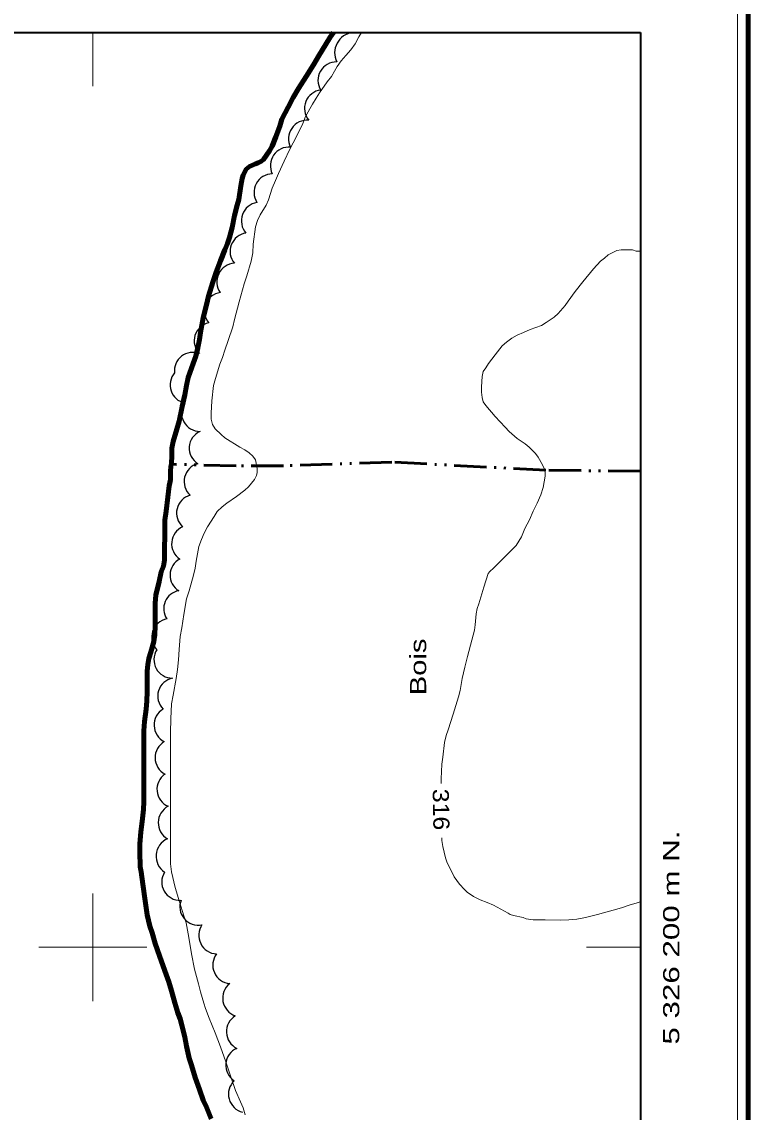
# Model space of a CAD drawing. Extents: x 240591 to 242335, y 5323482 to 5326937.
# Drawn here: x 242186.8 to 242321.7, y 5326169.4 to 5326371.9 of the extents above; entities that cross this region are included whole.
import ezdxf
from ezdxf.enums import TextEntityAlignment as Align

# ---------------------------------------------------------------- set-up
doc = ezdxf.new("R2010")
doc.units = 0
doc.header["$LTSCALE"] = 1.2
doc.linetypes.add('DASH_DOUBLE_DOT', pattern=[9.2, 5, -1.2, 0.3, -1.2, 0.3, -1.2])
doc.linetypes.add('LONG_DASHED', pattern=[7.5, 6, -1.5])
for name, color, linetype, lineweight in [('2', 7, 'Continuous', 13), ('4', 7, 'DASH_DOUBLE_DOT', 53), ('44', 7, 'Continuous', 25), ('60', 7, 'Continuous', 35), ('61', 7, 'Continuous', 13)]:
    doc.layers.add(name, color=color, linetype=linetype, lineweight=lineweight)

msp = doc.modelspace()

# ---------------------------------------------------------------- linework, layer by layer
at = {"layer": '2'}
for points in [[(242229.8, 5326330.6), (242230.2, 5326333.8), (242230.6, 5326335), (242231.1, 5326336), (242232.2, 5326337.8), (242232.6, 5326338.8), (242233.3, 5326341), (242233.9, 5326342.4), (242234.5, 5326343.7), (242235.5, 5326346), (242236.6, 5326348.2), (242237.8, 5326350.6), (242239, 5326353), (242239.5, 5326354.3), (242240.8, 5326356.6), (242241.5, 5326357.7), (242242.1, 5326358.7), (242243.5, 5326360.7), (242244.3, 5326361.7), (242244.9, 5326362.7), (242245.4, 5326363.6), (242246.1, 5326364.6), (242247, 5326365.6), (242247.9, 5326366.7), (242248.7, 5326367.8), (242249.4, 5326369.1), (242249.9, 5326369.9)], [(242228.3, 5326168.9), (242227.9, 5326170.2), (242227.4, 5326171.3), (242226.5, 5326173.4), (242225.6, 5326175.9), (242224.7, 5326178.7), (242223.7, 5326181.5), (242222.7, 5326184.1), (242221.6, 5326186.8), (242220.9, 5326188.6), (242220.6, 5326189.6), (242220, 5326191.7), (242219.6, 5326193.2), (242218.9, 5326195.9), (242218.3, 5326198.8), (242217.8, 5326201.8), (242217.3, 5326204.5), (242216.9, 5326205.8), (242216.1, 5326208.4), (242215.3, 5326211.1), (242214.6, 5326214), (242214.4, 5326215.5), (242214.4, 5326216.9), (242214.4, 5326219.9), (242214.4, 5326222.8), (242214.4, 5326226.1), (242214.4, 5326229.4), (242214.4, 5326233), (242214.4, 5326236.2), (242214.4, 5326239.9), (242214.5, 5326242.4), (242214.6, 5326245.2), (242214.9, 5326246.8), (242215.5, 5326249.9), (242215.7, 5326251.6), (242215.9, 5326253.4), (242216, 5326255.3), (242216.2, 5326257.7), (242216.5, 5326259.3), (242216.9, 5326261.8), (242217.4, 5326264.7), (242217.9, 5326266.2), (242218.7, 5326269.1), (242219, 5326270.4), (242219.2, 5326271.7), (242219.7, 5326274.4), (242220.2, 5326275.7), (242220.7, 5326276.9), (242221.3, 5326278.1), (242222.5, 5326280), (242223.1, 5326280.9), (242224, 5326281.8), (242224.9, 5326282.5), (242226.7, 5326283.7), (242228.2, 5326284.9), (242228.9, 5326285.5), (242230, 5326286.9), (242230.4, 5326287.6), (242230.5, 5326288.2), (242230.5, 5326288.9), (242230.2, 5326290.5), (242229.7, 5326291.2), (242229, 5326291.8), (242228.2, 5326292.4), (242227.3, 5326292.9), (242224.5, 5326294.6), (242223.8, 5326295.2), (242222.7, 5326296.3), (242222.2, 5326297.1), (242222, 5326298.1), (242222, 5326299.2), (242222.1, 5326301.5), (242222.4, 5326304.3), (242222.8, 5326305.6), (242223.6, 5326308.3), (242224.1, 5326309.5), (242224.5, 5326310.9), (242225.1, 5326312.7), (242226, 5326315.2), (242226.3, 5326316.6), (242227.2, 5326319.9), (242228.1, 5326323.2), (242228.6, 5326324.7), (242229.4, 5326327.4), (242229.7, 5326329), (242229.8, 5326330.6)]]:
    msp.add_lwpolyline(points, dxfattribs=at)
at = {"layer": '2', "linetype": 'LONG_DASHED'}
for points in [[(242272.3, 5326306), (242272.5, 5326306.9), (242273, 5326307.6), (242273.5, 5326308.4), (242274.7, 5326310), (242276, 5326311.7), (242276.8, 5326312.4), (242277.8, 5326313.1), (242278.8, 5326313.7), (242280, 5326314.2), (242281.2, 5326314.7), (242283.3, 5326315.5), (242284.2, 5326316), (242285.7, 5326317), (242286.4, 5326317.7), (242287.7, 5326319.2), (242288.3, 5326320), (242289.6, 5326321.8), (242291, 5326323.6), (242293, 5326326), (242294.3, 5326327.4), (242295, 5326328), (242295.7, 5326328.6), (242297.3, 5326329.4), (242298.1, 5326329.5), (242298.8, 5326329.5), (242300.2, 5326329.5), (242300.9, 5326329.3), (242301.7, 5326329.3)], [(242264.7, 5326230.4), (242264.7, 5326231.3), (242264.8, 5326234), (242265, 5326235.3), (242265.3, 5326238), (242265.6, 5326239.3), (242266, 5326240.4), (242266.9, 5326243.3), (242267.9, 5326246.5), (242268.2, 5326247.7), (242268.6, 5326249.9), (242269.1, 5326252), (242269.6, 5326254), (242270.4, 5326257), (242270.9, 5326258.9), (242271, 5326259.9), (242271.2, 5326261.9), (242271.4, 5326262.9), (242271.7, 5326263.8), (242272.6, 5326266.9), (242273.4, 5326269.4), (242273.7, 5326269.8), (242274.4, 5326270.4), (242275.7, 5326271.7), (242277.2, 5326273.2), (242278.6, 5326274.6), (242279.1, 5326275.4), (242279.6, 5326276.2), (242280.2, 5326277.8), (242281.1, 5326279.4), (242281.8, 5326281), (242282.5, 5326282.5), (242283.2, 5326284), (242283.6, 5326285.4), (242284, 5326287.5), (242284, 5326288.2), (242283.8, 5326288.9), (242283.5, 5326289.6), (242282.7, 5326291), (242282.2, 5326291.7), (242281, 5326292.9), (242280.3, 5326293.5), (242278.8, 5326294.5), (242277.3, 5326295.8), (242276.6, 5326296.6), (242274.7, 5326298.6), (242273, 5326300.6), (242272.5, 5326301.3), (242272.3, 5326302.1), (242272.2, 5326303.1), (242272.2, 5326304.1), (242272.3, 5326306)], [(242301.7, 5326208.5), (242301.3, 5326208.3), (242299.8, 5326207.9), (242298.2, 5326207.3), (242296.6, 5326206.9), (242293.7, 5326206.1), (242291.5, 5326205.5), (242289.9, 5326205.2), (242288.4, 5326205.1), (242286.8, 5326205), (242284, 5326205.1), (242281.8, 5326205.1), (242280.5, 5326205.3), (242279.9, 5326205.5), (242278.1, 5326205.9), (242277.5, 5326206.1), (242277.1, 5326206.3), (242274.4, 5326207.8), (242273.2, 5326208.3), (242271.9, 5326208.8), (242270.7, 5326209.4), (242269.5, 5326210.2), (242269, 5326210.7), (242268.1, 5326211.7), (242267.1, 5326213.1), (242266.7, 5326213.9), (242265.8, 5326215.7), (242265.5, 5326216.6), (242265, 5326218.7), (242264.8, 5326219.8), (242264.8, 5326220.3)]]:
    msp.add_lwpolyline(points, dxfattribs=at)
at = {"layer": '4', "linetype": 'Continuous', "lineweight": 90}
for points in [[(242244.7, 5326369.9), (242244.1, 5326369), (242243.2, 5326367.6), (242242, 5326365.7), (242241, 5326363.9), (242239.6, 5326361.7), (242238.2, 5326359.5), (242237.2, 5326357.8), (242236.3, 5326356), (242235.1, 5326353.8), (242234.7, 5326352.5), (242234, 5326350.5), (242233.3, 5326348.8), (242232.8, 5326347.9), (242231.7, 5326346.3), (242231.3, 5326346), (242230.7, 5326345.7), (242230.2, 5326345.5), (242229.1, 5326345), (242228.5, 5326344.5), (242228.2, 5326344), (242227.9, 5326343.4), (242227.7, 5326342.8), (242227.5, 5326341.4), (242227.1, 5326338.9), (242226.8, 5326337.8), (242226.3, 5326335.9), (242225.9, 5326333.7), (242225.4, 5326331.8), (242225, 5326330.7), (242224.5, 5326329.5), (242223.7, 5326327.5), (242222.9, 5326325.4), (242222.3, 5326323.5), (242221.5, 5326320.9), (242221.1, 5326319.3), (242220.5, 5326316.9), (242220, 5326314.2), (242219.8, 5326312.9), (242219.5, 5326311.3), (242219.1, 5326309.8), (242218.6, 5326308.4), (242217.7, 5326305.8), (242217.4, 5326304.3), (242217.1, 5326302.6), (242216.6, 5326300.4), (242216, 5326297.7), (242215.6, 5326296.2), (242214.9, 5326293.9), (242214.7, 5326292.7), (242214.7, 5326291.4), (242214.6, 5326289.7)], [(242214.4, 5326288.3), (242214.4, 5326286.8), (242214.2, 5326285.7), (242213.9, 5326283.6), (242213.6, 5326281), (242213.4, 5326279.3), (242213.4, 5326277.9), (242213.4, 5326276.1), (242213.3, 5326274.4), (242213.3, 5326271.9), (242213.1, 5326270.8), (242212.7, 5326269.7), (242212.3, 5326267.9), (242211.7, 5326265.4), (242211.6, 5326263.9), (242211.6, 5326262.3), (242211.6, 5326259.7), (242211.5, 5326258), (242211.3, 5326256.8), (242210.8, 5326254.8), (242210.4, 5326253.6), (242210.2, 5326252.5), (242210.1, 5326251.3), (242210.1, 5326249.9), (242210.1, 5326247.5), (242210, 5326245.7), (242209.9, 5326244.2), (242209.6, 5326241.9), (242209.5, 5326240.2), (242209.5, 5326238.2), (242209.5, 5326235.1), (242209.5, 5326232.5), (242209.5, 5326229.8), (242209.5, 5326227), (242209.4, 5326225.6), (242209.2, 5326223.9), (242208.9, 5326221.4), (242208.7, 5326219.2), (242208.7, 5326217.7), (242208.8, 5326214.9), (242209, 5326214), (242209.3, 5326211.7), (242209.7, 5326208.6), (242210.1, 5326206), (242210.6, 5326203.9), (242211, 5326202.7), (242211.6, 5326200.7), (242212.4, 5326198.4), (242213.4, 5326195.6), (242214.1, 5326193.6), (242214.6, 5326191.9), (242215.2, 5326189.7), (242215.8, 5326187.8), (242216.2, 5326186.7), (242216.5, 5326185.5), (242217.1, 5326183.3), (242217.4, 5326181.6), (242217.9, 5326179.4), (242218.3, 5326178.1), (242219, 5326175.8), (242219.8, 5326173.6), (242220.5, 5326171.6), (242221.1, 5326170.3), (242222, 5326168.1)], [(242214.6, 5326289.7), (242214.5, 5326289.4), (242214.4, 5326288.3)]]:
    msp.add_lwpolyline(points, dxfattribs=at)
at = {"layer": '4'}
msp.add_lwpolyline([(242301.7, 5326288.4), (242284.1, 5326288.6), (242255.5, 5326290.1), (242235.4, 5326289.4), (242226.6, 5326289.4), (242214.6, 5326289.7)], dxfattribs=at)
at = {"layer": '44'}
for centre, radius, start, end in [((242248.723, 5326366.11), 3.822, 97.47329, 206.0815), ((242245.241, 5326360.997), 3.433, 89.18247, 211.37505), ((242242.753, 5326355.794), 3.445, 97.39742, 219.35299), ((242231.044, 5326334.907), 3.459, 99.39087, 221.16121), ((242224.145, 5326318.183), 3.441, 98.10329, 220.02678), ((242222.231, 5326312.639), 3.409, 102.21586, 224.01713), ((242220.404, 5326286.477), 3.454, 105.1792, 227.25413), ((242214.836, 5326241.264), 3.459, 121.28851, 243.07297), ((242215, 5326235.206), 3.44, 120.18027, 242.29391), ((242215.344, 5326229.323), 3.439, 124.42069, 246.45095), ((242228.268, 5326184.315), 3.452, 121.78128, 243.72551)]:
    msp.add_arc(centre, radius, start, end, dxfattribs=at)
for centre, major_axis, ratio, start_param, end_param in [((242239.799, 5326350.17), (-0.197, -3.446), 0.999995, 3.1142531, 5.2450033), ((242236.402, 5326345.166), (-2.622, 2.227), 0.999596, 5.3206974, 7.4473389), ((242233.382, 5326340.189), (0.138, -3.449), 0.999995, 3.1195613, 5.2445601), ((242228.919, 5326329.225), (2.183, -2.657), 0.999984, 2.5936542, 4.7204313), ((242226.471, 5326323.581), (0.285, -3.433), 0.999995, 3.1142291, 5.2456293), ((242218.572, 5326307.071), (-2.578, -2.246), 0.999753, 3.634719, 5.6856978), ((242217.762, 5326304.438), (0.931, -3.29), 0.999938, 3.7256325, 5.788689), ((242219.883, 5326299.23), (1.635, -3.004), 0.999861, 3.6352066, 5.7895712), ((242221.306, 5326292.703), (-0.227, -3.403), 0.999753, 3.6331462, 5.7916317), ((242218.987, 5326280.626), (-3.346, 0.807), 0.999801, 5.2216763, 7.348405), ((242218.068, 5326274.95), (-3.428, 0.302), 0.999911, 5.2218424, 7.3470225), ((242217.754, 5326269.09), (0, -3.415), 0.999753, 3.633808, 5.7271318), ((242216.575, 5326262.865), (-1.607, -3.015), 0.999752, 3.8078177, 5.7891675), ((242214.364, 5326257.609), (-1.046, -3.258), 0.999751, 3.6381106, 5.7866674), ((242214.754, 5326253.391), (-2.47, -2.356), 0.998921, 4.9469885, 7.1031628), ((242215.466, 5326246.629), (-0.994, -3.271), 0.999752, 3.635639, 5.789139), ((242215.596, 5326223.129), (-3.456, 0.039), 0.996837, 5.2134502, 7.3389581), ((242215.323, 5326216.886), (-3.272, 1.445), 0.999964, 5.5497432, 7.6722565), ((242216.218, 5326212.126), (1.7, -2.97), 0.999938, 3.6374762, 5.7873018), ((242219.571, 5326207.517), (2.204, -2.613), 0.999938, 3.6363271, 5.7884508), ((242223.125, 5326202.216), (-3.094, -1.547), 0.999978, 5.2193403, 7.345551), ((242225.729, 5326196.681), (-3.159, -1.4), 0.999731, 5.2200659, 7.3475805), ((242227.593, 5326190.53), (2.246, -2.65), 0.999995, 3.1144058, 5.2447642), ((242228.152, 5326178.069), (-3.442, 0.291), 0.999556, 5.2177554, 7.3481972), ((242228.652, 5326172.723), (-3.458, 0.21), 0.999962, 5.5472771, 7.6722203)]:
    msp.add_ellipse(centre, major_axis=major_axis, ratio=ratio, start_param=start_param, end_param=end_param, dxfattribs=at)
at = {"layer": '60', "lineweight": 158}
msp.add_lwpolyline([(242321.7, 5323482.5), (240590.8, 5323482.5), (240590.8, 5326907.9), (242321.7, 5326907.9)], close=True, dxfattribs=at)
at = {"layer": '60', "lineweight": 13}
msp.add_lwpolyline([(240592.8, 5323484.5), (240592.8, 5326905.9), (242319.7, 5326905.9), (242319.7, 5323484.5)], close=True, dxfattribs=at)
at = {"layer": '60'}
msp.add_lwpolyline([(240610.8, 5326369.9), (242301.7, 5326369.9), (242301.7, 5323502.5), (240610.8, 5323502.5)], close=True, dxfattribs=at)
at = {"layer": '61'}
for p, q in [((242200, 5326369.9), (242200, 5326359.9)), ((242301.7, 5326200), (242291.7, 5326200))]:
    msp.add_line(p, q, dxfattribs=at)
for points in [[(242200, 5326210), (242200, 5326200), (242200, 5326190)], [(242190, 5326200), (242200, 5326200), (242210, 5326200)]]:
    msp.add_lwpolyline(points, dxfattribs=at)

# ---------------------------------------------------------------- texts
at = {"layer": '2', "width": 1.15}
msp.add_text('316', height=3, rotation=271.109, dxfattribs=at).set_placement((242263.1, 5326229.4))
at = {"layer": '44', "width": 1.35}
msp.add_text('Bois', height=3, rotation=90, dxfattribs=at).set_placement((242261.9, 5326246.8))
at = {"layer": '61', "width": 1.45}
msp.add_text('5 326 200 m N.', height=3, rotation=90, dxfattribs=at).set_placement((242308.9, 5326201.8), align=Align.CENTER)

doc.saveas('drawing.dxf')
